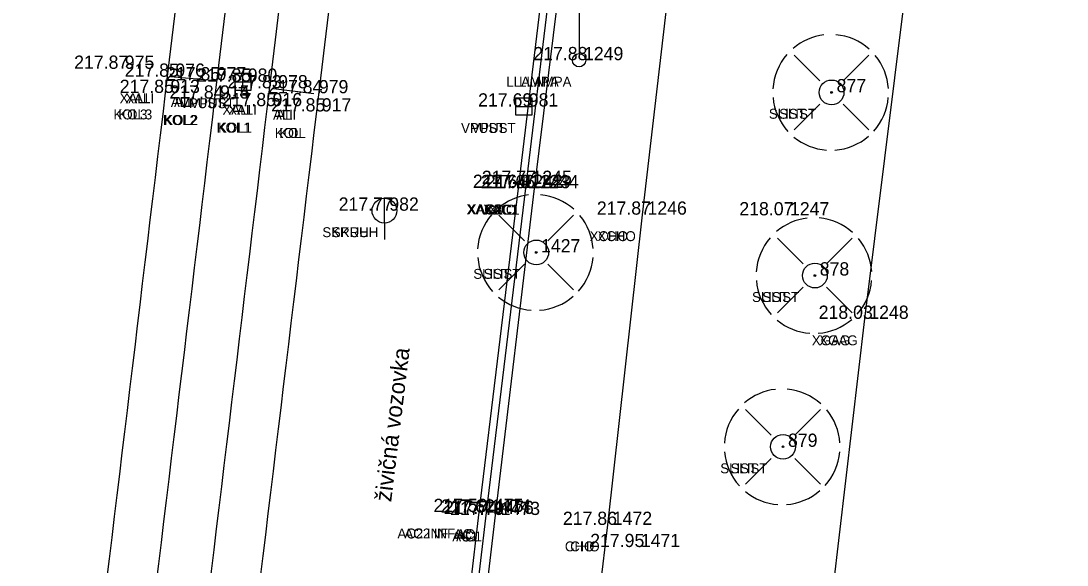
# Model space of a CAD drawing. Extents: x -471047 to -470889, y -1102859 to -1102000.
# Drawn here: x -470979.42 to -470947.78, y -1102543.92 to -1102527.47 of the extents above; entities that cross this region are included whole.
import ezdxf

# ---------------------------------------------------------------- set-up
doc = ezdxf.new("R2010")
doc.units = 0
for name, color, linetype in [('Vrstva 1', 7, 'Continuous'), ('Vrstva 16', 7, 'Continuous'), ('Vrstva 22', 7, 'Continuous'), ('Vrstva 23', 7, 'Continuous'), ('Vrstva 25', 7, 'Continuous'), ('Vrstva 29', 7, 'Continuous'), ('Vrstva 34', 7, 'Continuous'), ('Vrstva 35', 7, 'Continuous'), ('Vrstva 36', 7, 'Continuous'), ('Vrstva 38', 7, 'Continuous'), ('Vrstva 5', 7, 'Continuous'), ('Vrstva 6', 7, 'Continuous'), ('Vrstva 7', 7, 'Continuous'), ('Vrstva 8', 7, 'Continuous')]:
    doc.layers.add(name, color=color, linetype=linetype)

msp = doc.modelspace()

# ---------------------------------------------------------------- linework, layer by layer
at = {"layer": 'Vrstva 1'}
for points in [[(-471040.344, -1102858.385), (-471031.676, -1102846.187), (-471026.357, -1102838.629), (-471023.212, -1102833.975), (-471019.21, -1102827.465), (-471016.861, -1102823.272), (-471013.099, -1102815.912), (-471010.824, -1102810.955), (-471007.329, -1102802.292), (-471005.34, -1102796.515), (-471002.842, -1102787.838), (-471001.3, -1102780.997), (-471000.19, -1102774.713), (-470999.247, -1102768.204), (-470998.794, -1102764.784), (-470997.199, -1102751.812), (-470994.899, -1102732.807), (-470992.551, -1102713.262), (-470990.326, -1102694.887), (-470988.122, -1102676.57), (-470985.812, -1102657.305), (-470983.537, -1102638.407), (-470981.386, -1102620.622), (-470979.843, -1102608.014), (-470976.377, -1102579.253), (-470972.945, -1102550.69), (-470970.475, -1102530.206), (-470967.905, -1102508.801), (-470965.053, -1102485.131), (-470962.734, -1102465.9), (-470960.173, -1102444.812), (-470957.795, -1102425.103), (-470954.965, -1102401.839), (-470953.834, -1102392.574), (-470952.33, -1102379.985), (-470950.744, -1102366.853), (-470948.978, -1102352.106), (-470947.037, -1102335.844), (-470944.949, -1102318.462), (-470944.013, -1102310.745), (-470942.39, -1102297.267), (-470939.519, -1102273.45), (-470937.593, -1102257.43), (-470936.064, -1102244.81), (-470934.114, -1102228.634), (-470931.621, -1102207.856), (-470929.536, -1102190.857), (-470926.572, -1102166.31), (-470924.91, -1102152.663), (-470923.413, -1102140.333), (-470921.923, -1102127.669), (-470921.155, -1102120.084), (-470920.446, -1102109.574), (-470919.912, -1102099.137), (-470919.63, -1102088.981), (-470919.523, -1102081.193), (-470919.563, -1102070.395), (-470919.714, -1102064.236), (-470920.134, -1102054.704), (-470920.462, -1102047.615), (-470920.599, -1102044.52), (-470920.743, -1102041.873), (-470921.125, -1102034.455), (-470921.774, -1102030.337), (-470922.418, -1102027.787), (-470923.734, -1102023.93), (-470924.872, -1102021.434), (-470926.752, -1102018.182), (-470927.953, -1102016.45), (-470929.616, -1102014.424), (-470932.252, -1102011.756), (-470935.111, -1102009.425), (-470938.391, -1102007.371), (-470942.651, -1102005.401)], [(-471041.328, -1102857.18), (-471032.144, -1102844.242), (-471027.583, -1102837.763), (-471024.388, -1102833.028), (-471020.451, -1102826.6), (-471018.089, -1102822.378), (-471014.542, -1102815.445), (-471012.233, -1102810.418), (-471009.247, -1102803.108), (-471006.795, -1102796.098), (-471004.315, -1102787.532), (-471002.782, -1102780.723), (-471001.674, -1102774.458), (-471000.75, -1102768.095), (-471000.28, -1102764.601), (-470998.692, -1102751.741), (-470996.378, -1102732.635), (-470994.028, -1102713.058), (-470991.808, -1102694.749), (-470989.616, -1102676.447), (-470987.284, -1102657.013), (-470985.031, -1102638.272), (-470982.87, -1102620.431), (-470981.334, -1102607.933), (-470977.881, -1102579.263), (-470974.429, -1102550.492), (-470971.964, -1102530.054), (-470969.391, -1102508.607), (-470966.54, -1102484.984), (-470964.231, -1102465.853), (-470961.679, -1102444.752), (-470959.304, -1102425.078), (-470956.455, -1102401.634), (-470955.339, -1102392.489), (-470953.812, -1102379.71), (-470952.249, -1102366.808), (-470950.479, -1102352.023), (-470948.536, -1102335.868), (-470946.426, -1102318.233), (-470945.493, -1102310.531), (-470943.864, -1102297.013), (-470940.984, -1102273.071), (-470939.078, -1102257.195), (-470937.559, -1102244.684), (-470935.592, -1102228.353), (-470933.101, -1102207.653), (-470931.011, -1102190.57), (-470928.046, -1102166.021), (-470926.409, -1102152.578), (-470924.898, -1102140.121), (-470923.427, -1102127.544), (-470922.647, -1102119.826), (-470921.919, -1102109.229), (-470921.42, -1102099.134), (-470921.127, -1102089.016), (-470921.023, -1102081.453), (-470921.061, -1102070.468), (-470921.209, -1102064.314), (-470921.666, -1102053.966), (-470922.156, -1102043.345), (-470922.299, -1102039.934), (-470922.637, -1102034.36), (-470923.091, -1102031.241), (-470923.847, -1102028.247), (-470925.083, -1102024.594), (-470926.222, -1102022.086), (-470928.04, -1102018.943), (-470929.138, -1102017.357), (-470930.929, -1102015.175), (-470933.062, -1102013.049), (-470936.379, -1102010.368), (-470939.169, -1102008.662), (-470942.899, -1102006.906), (-470945.661, -1102005.908)], [(-471043.557, -1102855.955), (-471035.129, -1102844.026), (-471029.872, -1102836.499), (-471026.577, -1102831.578), (-471022.675, -1102825.415), (-471020.123, -1102821.053), (-471016.667, -1102814.59), (-471014.208, -1102809.45), (-471011.177, -1102802.451), (-471008.55, -1102795.333), (-471006.082, -1102787.209), (-471004.464, -1102780.376), (-471003.265, -1102774.167), (-471002.327, -1102767.948), (-471001.636, -1102762.527), (-471000.297, -1102751.605), (-470997.959, -1102732.524), (-470995.602, -1102712.802), (-470993.412, -1102694.623), (-470991.21, -1102676.17), (-470988.891, -1102656.857), (-470986.625, -1102638.083), (-470984.455, -1102620.195), (-470982.936, -1102607.733), (-470979.497, -1102579.223), (-470976.023, -1102550.279), (-470973.554, -1102529.822), (-470970.991, -1102508.497), (-470968.146, -1102484.787), (-470965.835, -1102465.72), (-470963.284, -1102444.529), (-470960.91, -1102424.942), (-470958.043, -1102401.343), (-470956.946, -1102392.356), (-470955.396, -1102379.408), (-470953.851, -1102366.636), (-470952.049, -1102351.733), (-470950.124, -1102335.611), (-470948.034, -1102318.083), (-470947.094, -1102310.328), (-470945.421, -1102296.51), (-470942.58, -1102272.848), (-470940.675, -1102256.948), (-470939.176, -1102244.526), (-470937.187, -1102228.174), (-470934.708, -1102207.467), (-470932.621, -1102190.433), (-470929.634, -1102165.778), (-470928.004, -1102152.415), (-470926.45, -1102139.595), (-470925.003, -1102127.418), (-470924.249, -1102119.695), (-470923.515, -1102109.093), (-470923.018, -1102099.069), (-470922.711, -1102088.911), (-470922.643, -1102081.356), (-470922.797, -1102070.414), (-470923.018, -1102064.454), (-470923.52, -1102053.203), (-470923.823, -1102047.529), (-470924.123, -1102041.506), (-470924.462, -1102037.486), (-470924.934, -1102031.904), (-470925.664, -1102028.672), (-470926.771, -1102025.506), (-470927.959, -1102022.914), (-470929.674, -1102020.028), (-470930.76, -1102018.498), (-470932.447, -1102016.478), (-470935.215, -1102013.816), (-470937.644, -1102011.98), (-470940.381, -1102010.371), (-470943.968, -1102008.669), (-470947.145, -1102007.524), (-470950.874, -1102006.74)], [(-471044.756, -1102855.056), (-471036.376, -1102843.177), (-471031.167, -1102835.741), (-471027.859, -1102830.8), (-471023.934, -1102824.593), (-471021.43, -1102820.312), (-471018.011, -1102813.91), (-471015.536, -1102808.75), (-471012.578, -1102801.897), (-471009.95, -1102794.77), (-471007.561, -1102786.914), (-471005.936, -1102780.074), (-471004.727, -1102773.818), (-471003.828, -1102767.827), (-471003.121, -1102762.345), (-471001.787, -1102751.467), (-470999.446, -1102732.348), (-470997.073, -1102712.539), (-470994.902, -1102694.521), (-470992.696, -1102676.023), (-470990.376, -1102656.68), (-470988.131, -1102638.071), (-470985.947, -1102620.018), (-470984.417, -1102607.512), (-470980.993, -1102579.08), (-470977.514, -1102550.137), (-470975.048, -1102529.649), (-470972.488, -1102508.37), (-470969.618, -1102484.508), (-470967.34, -1102465.669), (-470964.767, -1102444.39), (-470962.402, -1102424.781), (-470959.534, -1102401.193), (-470958.432, -1102392.151), (-470956.883, -1102379.208), (-470955.335, -1102366.424), (-470953.535, -1102351.506), (-470951.606, -1102335.399), (-470949.519, -1102317.94), (-470948.575, -1102310.159), (-470946.889, -1102296.144), (-470944.056, -1102272.618), (-470942.139, -1102256.659), (-470940.657, -1102244.341), (-470938.638, -1102227.749), (-470936.19, -1102207.298), (-470934.102, -1102190.255), (-470931.124, -1102165.639), (-470929.492, -1102152.254), (-470927.915, -1102139.252), (-470926.46, -1102127.103), (-470925.74, -1102119.604), (-470925.012, -1102108.913), (-470924.523, -1102099.054), (-470924.217, -1102088.866), (-470924.148, -1102081.334), (-470924.301, -1102070.391), (-470924.518, -1102064.43), (-470924.97, -1102054.435), (-470925.588, -1102041.569), (-470925.963, -1102035.313), (-470926.405, -1102032.225), (-470927.078, -1102029.198), (-470928.123, -1102026.148), (-470929.318, -1102023.558), (-470930.84, -1102020.97), (-470931.868, -1102019.515), (-470933.443, -1102017.605), (-470936.26, -1102014.885), (-470938.429, -1102013.255), (-470941.213, -1102011.639), (-470944.847, -1102009.927), (-470947.723, -1102008.912), (-470951.444, -1102008.161), (-470954.511, -1102007.931), (-470957.895, -1102008.041)]]:
    msp.add_spline(points, degree=3, dxfattribs=at)
at = {"layer": 'Vrstva 16'}
for p, q in [((-470955.26, -1102529.279), (-470956.034, -1102528.504)), ((-470954.55, -1102529.279), (-470953.774, -1102528.504)), ((-470955.26, -1102529.989), (-470956.034, -1102530.764)), ((-470954.55, -1102529.989), (-470953.774, -1102530.764)), ((-470964.192, -1102534.118), (-470964.968, -1102533.343)), ((-470963.482, -1102534.118), (-470962.708, -1102533.343)), ((-470955.764, -1102534.816), (-470956.54, -1102534.041)), ((-470955.054, -1102534.816), (-470954.28, -1102534.041)), ((-470964.192, -1102534.828), (-470964.968, -1102535.603)), ((-470963.482, -1102534.828), (-470962.708, -1102535.603)), ((-470955.764, -1102535.526), (-470956.54, -1102536.301)), ((-470955.054, -1102535.526), (-470954.28, -1102536.301)), ((-470956.728, -1102539.994), (-470957.502, -1102539.219)), ((-470956.018, -1102539.994), (-470955.242, -1102539.219)), ((-470956.728, -1102540.704), (-470957.502, -1102541.479)), ((-470956.018, -1102540.704), (-470955.242, -1102541.479))]:
    msp.add_line(p, q, dxfattribs=at)
for centre, radius in [((-470954.904, -1102529.634), 0.375), ((-470954.904, -1102529.634), 0.025), ((-470954.904, -1102529.634), 0.025), ((-470963.837, -1102534.473), 0.375), ((-470963.837, -1102534.473), 0.025), ((-470963.837, -1102534.473), 0.025), ((-470955.409, -1102535.171), 0.375), ((-470955.409, -1102535.171), 0.025), ((-470955.409, -1102535.171), 0.025), ((-470956.372, -1102540.349), 0.375), ((-470956.372, -1102540.349), 0.025), ((-470956.372, -1102540.349), 0.025)]:
    msp.add_circle(centre, radius, dxfattribs=at)
for centre, start, end in [((-470954.93, -1102529.634), 96.7144, 130.447), ((-470954.93, -1102529.634), 48.1897, 84.9117), ((-470954.93, -1102529.634), 139.23, 176.4602), ((-470954.93, -1102529.634), 3.8615, 39.6013), ((-470954.93, -1102529.634), 184.9408, 222.2827), ((-470954.93, -1102529.634), 318.1086, 355.0481), ((-470954.93, -1102529.634), 230.4703, 265.8356), ((-470954.93, -1102529.634), 274.1732, 310.7861), ((-470963.862, -1102534.473), 96.7144, 130.447), ((-470963.862, -1102534.473), 48.1897, 84.9117), ((-470963.862, -1102534.473), 139.23, 176.4602), ((-470963.862, -1102534.473), 3.8615, 39.6013), ((-470955.435, -1102535.171), 96.7144, 130.447), ((-470955.435, -1102535.171), 48.1897, 84.9117), ((-470955.435, -1102535.171), 139.23, 176.4602), ((-470955.435, -1102535.171), 3.8615, 39.6013), ((-470963.862, -1102534.473), 184.9408, 222.2827), ((-470963.862, -1102534.473), 318.1086, 355.0481), ((-470955.435, -1102535.171), 184.9408, 222.2827), ((-470955.435, -1102535.171), 318.1086, 355.0481), ((-470963.862, -1102534.473), 230.4703, 265.8356), ((-470963.862, -1102534.473), 274.1732, 310.7861), ((-470955.435, -1102535.171), 230.4703, 265.8356), ((-470955.435, -1102535.171), 274.1732, 310.7861), ((-470956.398, -1102540.349), 96.7144, 130.447), ((-470956.398, -1102540.349), 48.1897, 84.9117), ((-470956.398, -1102540.349), 139.23, 176.4602), ((-470956.398, -1102540.349), 3.8615, 39.6013), ((-470956.398, -1102540.349), 184.9408, 222.2827), ((-470956.398, -1102540.349), 318.1086, 355.0481), ((-470956.398, -1102540.349), 230.4703, 265.8356), ((-470956.398, -1102540.349), 274.1732, 310.7861)]:
    msp.add_arc(centre, 1.75, start, end, dxfattribs=at)
at = {"layer": 'Vrstva 23'}
msp.add_line((-470962.541, -1102525.962), (-470962.541, -1102528.462), dxfattribs=at)
msp.add_circle((-470962.541, -1102528.662), 0.2, dxfattribs=at)
at = {"layer": 'Vrstva 25'}
for p, q in [((-470972.956, -1102529.064), (-470972.956, -1102529.564)), ((-470972.456, -1102529.064), (-470972.956, -1102529.064)), ((-470972.456, -1102529.564), (-470972.456, -1102529.064)), ((-470972.956, -1102529.314), (-470972.456, -1102529.314)), ((-470972.956, -1102529.564), (-470972.456, -1102529.564)), ((-470964.46, -1102529.809), (-470964.46, -1102530.309)), ((-470963.96, -1102529.809), (-470964.46, -1102529.809)), ((-470964.46, -1102530.059), (-470963.96, -1102530.059)), ((-470963.96, -1102530.309), (-470963.96, -1102529.809)), ((-470964.46, -1102530.309), (-470963.96, -1102530.309)), ((-470968.427, -1102533.584), (-470968.427, -1102532.834)), ((-470968.427, -1102533.584), (-470968.427, -1102534.084))]:
    msp.add_line(p, q, dxfattribs=at)
msp.add_circle((-470968.427, -1102533.209), 0.375, dxfattribs=at)
at = {"layer": 'Vrstva 29'}
for p, q in [((-470974.895, -1102529.155), (-470973.645, -1102529.267)), ((-470971.786, -1102529.515), (-470970.561, -1102529.662))]:
    msp.add_line(p, q, dxfattribs=at)
at = {"layer": 'Vrstva 34'}
for p, q in [((-470962.54, -1102528.66), (-470962.54, -1102528.66)), ((-470976.43, -1102528.92), (-470976.43, -1102528.92)), ((-470974.9, -1102529.16), (-470974.9, -1102529.16)), ((-470973.65, -1102529.27), (-470973.65, -1102529.27)), ((-470972.71, -1102529.31), (-470972.71, -1102529.31)), ((-470975.05, -1102529.65), (-470975.05, -1102529.65)), ((-470971.79, -1102529.51), (-470971.79, -1102529.51)), ((-470970.56, -1102529.66), (-470970.56, -1102529.66)), ((-470954.9, -1102529.63), (-470954.9, -1102529.63)), ((-470973.55, -1102529.82), (-470973.55, -1102529.82)), ((-470973.55, -1102529.82), (-470973.55, -1102529.82)), ((-470971.96, -1102530.05), (-470971.96, -1102530.05)), ((-470964.21, -1102530.06), (-470964.21, -1102530.06)), ((-470970.47, -1102530.21), (-470970.47, -1102530.21)), ((-470964.37, -1102532.52), (-470964.37, -1102532.52)), ((-470964.15, -1102532.53), (-470964.15, -1102532.53)), ((-470964.1, -1102532.4), (-470964.1, -1102532.4)), ((-470963.89, -1102532.53), (-470963.89, -1102532.53)), ((-470968.43, -1102533.21), (-470968.43, -1102533.21)), ((-470960.62, -1102533.33), (-470960.62, -1102533.33)), ((-470956.31, -1102533.35), (-470956.31, -1102533.35)), ((-470963.84, -1102534.47), (-470963.84, -1102534.47)), ((-470955.41, -1102535.17), (-470955.41, -1102535.17)), ((-470953.91, -1102536.48), (-470953.91, -1102536.48)), ((-470956.37, -1102540.35), (-470956.37, -1102540.35)), ((-470965.56, -1102542.32), (-470965.56, -1102542.32)), ((-470965.34, -1102542.34), (-470965.34, -1102542.34)), ((-470965.25, -1102542.38), (-470965.25, -1102542.38)), ((-470965.06, -1102542.41), (-470965.06, -1102542.41)), ((-470961.67, -1102542.71), (-470961.67, -1102542.71)), ((-470960.82, -1102543.38), (-470960.82, -1102543.38))]:
    msp.add_line(p, q, dxfattribs=at)
at = {"layer": 'Vrstva 5'}
for p, q in [((-470964.373, -1102532.525), (-470962.822, -1102519.695)), ((-470965.561, -1102542.324), (-470964.373, -1102532.525)), ((-470967.155, -1102555.569), (-470965.561, -1102542.324))]:
    msp.add_line(p, q, dxfattribs=at)
at = {"layer": 'Vrstva 6'}
for p, q in [((-470952.301, -1102523.614), (-470953.909, -1102536.477)), ((-470953.909, -1102536.477), (-470954.875, -1102544.737))]:
    msp.add_line(p, q, dxfattribs=at)
at = {"layer": 'Vrstva 7'}
for p, q in [((-470963.893, -1102532.535), (-470962.282, -1102519.65)), ((-470965.064, -1102542.413), (-470963.893, -1102532.535)), ((-470966.667, -1102555.716), (-470965.064, -1102542.413))]:
    msp.add_line(p, q, dxfattribs=at)
at = {"layer": 'Vrstva 8'}
for p, q in [((-470964.153, -1102532.528), (-470962.594, -1102519.608)), ((-470960.623, -1102533.331), (-470959.075, -1102520)), ((-470965.341, -1102542.335), (-470964.153, -1102532.528)), ((-470961.673, -1102542.71), (-470960.623, -1102533.331)), ((-470966.92, -1102555.628), (-470965.341, -1102542.335)), ((-470963.227, -1102555.483), (-470961.673, -1102542.71))]:
    msp.add_line(p, q, dxfattribs=at)

# ---------------------------------------------------------------- texts
at = {"layer": 'Vrstva 22'}
msp.add_text('živičná vozovka', height=0.5, rotation=83.0936, dxfattribs=at).set_placement((-470968.225, -1102542.031))
at = {"layer": 'Vrstva 35'}
for s, p in [('LLAMPA', (-470964.74, -1102529.46)), ('LLAMPA', (-470964.354, -1102529.46)), ('XALI', (-470976.438, -1102529.96)), ('XALI', (-470976.264, -1102529.96)), ('ALI', (-470974.888, -1102530.07)), ('ALI', (-470974.789, -1102530.07)), ('VPUST', (-470974.61, -1102530.11)), ('VPUST', (-470974.299, -1102530.11)), ('XALI', (-470973.328, -1102530.31)), ('XALI', (-470973.154, -1102530.31)), ('KOL3', (-470976.625, -1102530.45)), ('KOL3', (-470976.478, -1102530.45)), ('KOL2', (-470975.125, -1102530.62)), ('KOL2', (-470975.125, -1102530.62)), ('KOL2', (-470975.091, -1102530.62)), ('KOL2', (-470975.091, -1102530.62)), ('ALI', (-470971.798, -1102530.46)), ('ALI', (-470971.699, -1102530.46)), ('SLIST', (-470956.8, -1102530.43)), ('SLIST', (-470956.489, -1102530.43)), ('KOL1', (-470973.502, -1102530.85)), ('KOL1', (-470973.46, -1102530.85)), ('VPUST', (-470966.11, -1102530.86)), ('VPUST', (-470965.799, -1102530.86)), ('KOL', (-470971.745, -1102531.01)), ('KOL', (-470971.609, -1102531.01)), ('XAC2', (-470965.945, -1102533.32)), ('XAC2', (-470965.911, -1102533.32)), ('XAC', (-470965.439, -1102533.33)), ('XAC1', (-470965.432, -1102533.33)), ('XAC1', (-470965.39, -1102533.33)), ('XAC', (-470965.289, -1102533.33)), ('SKRUH', (-470970.305, -1102534.01)), ('SKRUH', (-470970.019, -1102534.01)), ('XCHO', (-470962.221, -1102534.13)), ('XCHO', (-470961.984, -1102534.13)), ('SLIST', (-470965.74, -1102535.27)), ('SLIST', (-470965.429, -1102535.27)), ('SLIST', (-470957.31, -1102535.97)), ('SLIST', (-470956.999, -1102535.97)), ('XGAG', (-470955.5, -1102537.28)), ('XGAG', (-470955.274, -1102537.28)), ('SLIST', (-470958.27, -1102541.15)), ('SLIST', (-470957.959, -1102541.15)), ('AC2 INF', (-470968.035, -1102543.12)), ('AC2 INF', (-470967.824, -1102543.12)), ('AC1', (-470966.377, -1102543.21)), ('AC', (-470966.329, -1102543.14)), ('AC1', (-470966.26, -1102543.21)), ('AC', (-470966.254, -1102543.14)), ('CHO', (-470962.971, -1102543.51)), ('CHO', (-470962.809, -1102543.51))]:
    msp.add_text(s, height=0.3, dxfattribs=at).set_placement(p)
at = {"layer": 'Vrstva 36'}
for s, p in [(' 1249', (-470962.54, -1102528.66)), (' 975', (-470976.43, -1102528.92)), (' 976', (-470974.9, -1102529.16)), (' 977', (-470973.65, -1102529.27)), (' 980', (-470972.71, -1102529.31)), (' 978', (-470971.79, -1102529.51)), (' 913', (-470975.05, -1102529.65)), (' 914', (-470973.55, -1102529.82)), (' 915', (-470973.55, -1102529.82)), (' 979', (-470970.56, -1102529.66)), (' 877', (-470954.9, -1102529.63)), (' 916', (-470971.96, -1102530.05)), (' 981', (-470964.21, -1102530.06)), (' 917', (-470970.47, -1102530.21)), (' 1242', (-470964.37, -1102532.52)), (' 1243', (-470964.15, -1102532.53)), (' 1245', (-470964.1, -1102532.4)), (' 1244', (-470963.89, -1102532.53)), (' 982', (-470968.43, -1102533.21)), (' 1246', (-470960.62, -1102533.33)), (' 1247', (-470956.31, -1102533.35)), (' 1427', (-470963.84, -1102534.47)), (' 878', (-470955.41, -1102535.17)), (' 1248', (-470953.91, -1102536.48)), (' 879', (-470956.37, -1102540.35)), (' 1475', (-470965.56, -1102542.32)), (' 1474', (-470965.34, -1102542.34)), (' 1476', (-470965.25, -1102542.38)), (' 1473', (-470965.06, -1102542.41)), (' 1472', (-470961.67, -1102542.71)), (' 1471', (-470960.82, -1102543.38))]:
    msp.add_text(s, height=0.4, dxfattribs=at).set_placement(p)
at = {"layer": 'Vrstva 38'}
for s, p in [('217.88 ', (-470963.924, -1102528.66)), ('217.87 ', (-470977.813, -1102528.92)), ('217.85 ', (-470976.284, -1102529.16)), ('217.85 ', (-470975.034, -1102529.27)), ('217.85 ', (-470974.094, -1102529.31)), ('217.83 ', (-470973.173, -1102529.51)), ('217.85 ', (-470976.434, -1102529.65)), ('217.84 ', (-470974.932, -1102529.82)), ('217.84 ', (-470974.932, -1102529.82)), ('217.84 ', (-470971.942, -1102529.66)), ('217.85 ', (-470973.344, -1102530.05)), ('217.69 ', (-470965.594, -1102530.06)), ('217.85 ', (-470971.854, -1102530.21)), ('217.64 ', (-470965.752, -1102532.52)), ('217.66 ', (-470965.51, -1102532.53)), ('217.77 ', (-470965.483, -1102532.4)), ('217.81 ', (-470965.36, -1102532.53)), ('217.77 ', (-470969.813, -1102533.21)), ('217.87 ', (-470962.003, -1102533.33)), ('218.07 ', (-470957.693, -1102533.35)), ('218.03 ', (-470955.293, -1102536.48)), ('217.59 ', (-470966.944, -1102542.32)), ('217.62 ', (-470966.721, -1102542.34)), ('217.74 ', (-470966.632, -1102542.38)), ('217.79 ', (-470966.444, -1102542.41)), ('217.86 ', (-470963.03, -1102542.71)), ('217.95 ', (-470962.204, -1102543.38))]:
    msp.add_text(s, height=0.4, dxfattribs=at).set_placement(p)

doc.saveas('drawing.dxf')
